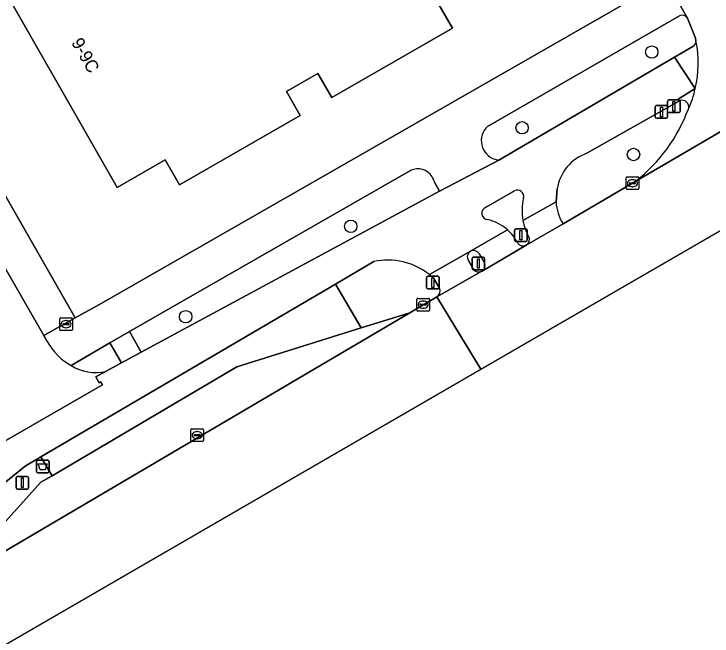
# Model space of a CAD drawing. Extents: x 158455 to 159797, y 387218 to 388672.
# Drawn here: x 159062 to 159117.1, y 387353.6 to 387402.7 of the extents above; entities that cross this region are included whole.
import ezdxf

# ---------------------------------------------------------------- set-up
doc = ezdxf.new("R2010")
doc.units = 0
for name, color, linetype in [('IMGEO_Afvalbak', 7, 'Continuous'), ('IMGEO_Berm_groen', 7, 'Continuous'), ('IMGEO_Boom', 7, 'Continuous'), ('IMGEO_Brandkraan', 7, 'Continuous'), ('IMGEO_Erf', 7, 'Continuous'), ('IMGEO_Fietspad_gesloten', 7, 'Continuous'), ('IMGEO_Fietspad_open', 7, 'Continuous'), ('IMGEO_Groenvoorziening', 7, 'Continuous'), ('IMGEO_Kolk', 7, 'Continuous'), ('IMGEO_Lichtmast', 7, 'Continuous'), ('IMGEO_Pand', 7, 'Continuous'), ('IMGEO_Pand_nummerreeks', 7, 'Continuous'), ('IMGEO_Rijbaan_lokaal_gesloten', 7, 'Continuous'), ('IMGEO_Rijbaan_lokaal_open', 7, 'Continuous'), ('IMGEO_Verkeerseiland_groen', 7, 'Continuous'), ('IMGEO_Verkeerseiland_open', 7, 'Continuous'), ('IMGEO_Verkeersregelinstallatiepaal', 7, 'Continuous'), ('IMGEO_Voetpad_open', 7, 'Continuous')]:
    doc.layers.add(name, color=color, linetype=linetype)

msp = doc.modelspace()

# ---------------------------------------------------------------- linework, layer by layer
at = {"layer": 'IMGEO_Afvalbak'}
for p, q in [((159063.771, 387366.587), (159063.771, 387367.387)), ((159063.771, 387367.387), (159063.771, 387366.587)), ((159063.871, 387367.487), (159064.661, 387367.487)), ((159064.661, 387367.487), (159063.871, 387367.487)), ((159064.761, 387367.387), (159064.761, 387366.587)), ((159064.761, 387366.587), (159064.761, 387367.387)), ((159064.661, 387366.487), (159063.871, 387366.487)), ((159063.871, 387366.487), (159064.661, 387366.487))]:
    msp.add_line(p, q, dxfattribs=at)
msp.add_lwpolyline([(159063.914, 387367.201), (159064.618, 387367.201), (159064.469, 387366.731), (159064.063, 387366.731), (159063.914, 387367.201)], dxfattribs=at)
for centre, start, end in [((159063.871, 387367.387), 90, 180), ((159063.871, 387367.387), 90, 180), ((159064.661, 387367.387), 0, 90), ((159064.661, 387367.387), 360, 90), ((159063.871, 387366.587), 180, 270), ((159063.871, 387366.587), 180, 270), ((159064.661, 387366.587), 270, 0), ((159064.661, 387366.587), 270, 0)]:
    msp.add_arc(centre, 0.1, start, end, dxfattribs=at)
at = {"layer": 'IMGEO_Berm_groen'}
for points in [[(159114.509, 387402.534), (159099.35, 387393.809)], [(159115.799, 387400.557), (159115.753, 387400.768), (159115.144, 387402.351)], [(159114.102, 387399.28), (159115.554, 387400.104)], [(159100.242, 387391.149), (159114.102, 387399.28)], [(159093.275, 387390.319), (159071.117, 387377.621), (159072.04, 387376.001), (159095.556, 387388.708)], [(159095.556, 387388.708), (159095.195, 387389.355)]]:
    msp.add_lwpolyline(points, dxfattribs=at)
msp.add_lwpolyline([(159038.659, 387347.178), (159053.231, 387355.576), (159056.88, 387357.739), (159064.12, 387365.736), (159065.004, 387366.253), (159064.118, 387367.746), (159062.871, 387366.998), (159053.387, 387359.328), (159051.34, 387358.173), (159035.521, 387349.101), (159024.831, 387342.952), (159003.155, 387330.485), (159003.462, 387329.964), (159005.167, 387327.132), (159026.581, 387340.034), (159027.914, 387340.837), (159037.173, 387346.301)], close=True, dxfattribs=at)
for centre, radius, start, end in [((159114.714, 387402.051), 0.525, 34.8953, 112.9519), ((159115.267, 387400.552), 0.532, 302.6578, 0.5297), ((159100.403, 387392.682), 1.542, 133.071, 252.4441), ((159100.405, 387392.699), 1.558, 252.5757, 264.0082), ((159093.873, 387389.167), 1.298, 31.0177, 117.437), ((159093.731, 387389.002), 1.506, 13.5475, 33.6237)]:
    msp.add_arc(centre, radius, start, end, dxfattribs=at)
at = {"layer": 'IMGEO_Boom'}
for centre in [(159112.312, 387399.672), (159102.081, 387393.697), (159110.87, 387391.593), (159088.565, 387385.923), (159075.542, 387378.796)]:
    msp.add_circle(centre, 0.489, dxfattribs=at)
at = {"layer": 'IMGEO_Brandkraan'}
for p, q in [((159065.603, 387377.783), (159065.603, 387378.635)), ((159065.678, 387378.709), (159066.53, 387378.709)), ((159066.604, 387378.635), (159066.604, 387377.783)), ((159065.862, 387378.203), (159065.862, 387378.215)), ((159066.3, 387378.166), (159065.902, 387378.166)), ((159065.905, 387378.252), (159066.303, 387378.252)), ((159066.091, 387378.489), (159066.116, 387378.489)), ((159066.346, 387378.215), (159066.346, 387378.203)), ((159066.53, 387377.709), (159065.678, 387377.709)), ((159066.114, 387377.929), (159066.089, 387377.929))]:
    msp.add_line(p, q, dxfattribs=at)
for points in [[(159065.603, 387377.783), (159065.603, 387378.635)], [(159065.678, 387378.709), (159066.53, 387378.709)], [(159066.604, 387378.635), (159066.604, 387377.783)], [(159066.53, 387377.709), (159065.678, 387377.709)]]:
    msp.add_lwpolyline(points, dxfattribs=at)
for centre, radius, start, end in [((159065.68, 387378.633), 0.0765, 91.552, 178.448), ((159065.68, 387378.633), 0.0765, 91.552, 178.448), ((159066.528, 387378.633), 0.0765, 1.552, 88.448), ((159066.528, 387378.633), 0.0765, 1.552, 88.448), ((159065.902, 387378.212), 0.0403, 85.8775, 175.7526), ((159065.899, 387378.202), 0.0366, 178.938, 274.7102), ((159066.303, 387378.209), 0.043, 264.8664, 352.4533), ((159066.307, 387378.214), 0.0386, 1.7309, 96.639), ((159065.68, 387377.785), 0.0765, 181.552, 268.448), ((159065.68, 387377.785), 0.0765, 181.552, 268.448), ((159066.528, 387377.785), 0.0765, 271.552, 358.448), ((159066.528, 387377.785), 0.0765, 271.552, 358.448)]:
    msp.add_arc(centre, radius, start, end, dxfattribs=at)
for centre, major_axis, ratio, start_param, end_param in [((159066.09, 387378.209), (-0.387, 0.002), 0.722429, 4.712389, 7.853982), ((159066.115, 387378.209), (-0.39, 0.002), 0.717154, 1.570796, 4.712389)]:
    msp.add_ellipse(centre, major_axis=major_axis, ratio=ratio, start_param=start_param, end_param=end_param, dxfattribs=at)
at = {"layer": 'IMGEO_Erf'}
for points in [[(159055.639, 387398.219), (159066.827, 387378.71), (159068.702, 387379.738), (159112.122, 387404.631), (159083.935, 387453.791)], [(159095.447, 387403.559), (159096.601, 387401.547), (159087.066, 387396.08), (159085.964, 387397.979), (159083.497, 387396.551), (159084.577, 387394.669), (159075.053, 387389.205), (159073.918, 387391.164), (159070.135, 387388.988), (159059.41, 387407.722)]]:
    msp.add_lwpolyline(points, dxfattribs=at)
at = {"layer": 'IMGEO_Fietspad_gesloten'}
for points in [[(159115.554, 387400.104), (159114.102, 387399.28), (159115.738, 387396.797)], [(159107.2, 387391.685), (159114.499, 387395.824), (159114.395, 387395.952), (159115.738, 387396.797), (159114.102, 387399.28), (159100.242, 387391.149), (159095.556, 387388.708), (159072.04, 387376.001), (159070.47, 387375.153), (159069.219, 387374.477), (159068.465, 387374.062), (159068.718, 387373.591), (159068.847, 387373.665), (159068.984, 387373.414), (159060.337, 387368.463), (159059.986, 387368.507)], [(159115.738, 387396.797), (159114.395, 387395.952), (159114.499, 387395.824)], [(159099.198, 387387.41), (159101.474, 387388.712)], [(159102.151, 387386.373), (159104.761, 387387.852), (159104.848, 387388.885)], [(159104.761, 387387.852), (159102.151, 387386.373)], [(159102.415, 387384.438), (159105.321, 387386.122)], [(159094.769, 387382.118), (159098.009, 387383.961), (159100.919, 387385.658)], [(159003.155, 387330.485), (159024.831, 387342.952), (159035.521, 387349.101), (159051.34, 387358.173), (159053.387, 387359.328), (159062.871, 387366.998), (159064.118, 387367.746), (159087.366, 387381.363), (159090.378, 387383.144)]]:
    msp.add_lwpolyline(points, dxfattribs=at)
for centre, radius, start, end in [((159115.267, 387400.552), 0.532, 302.6578, 0.5297), ((159107.355, 387398.813), 8.622, 346.4742, 11.6669), ((159109.652, 387397.919), 6.189, 333.702, 349.5555), ((159114.71, 387395.349), 0.52, 340.6614, 113.9267), ((159108.355, 387388.327), 3.552, 108.9861, 170.9534), ((159101.726, 387388.293), 0.489, 344.4726, 121.0055), ((159106.338, 387387.16), 4.26, 166.4022, 190.652), ((159108.383, 387388.069), 3.629, 183.4272, 212.4463), ((159099.41, 387386.955), 0.502, 114.9482, 263.0587), ((159098.586, 387383.015), 3.525, 48.559, 77.4964), ((159106.325, 387387.16), 4.247, 190.6791, 208.5526), ((159102.145, 387384.877), 0.515, 301.5865, 29.4079), ((159091.501, 387378.041), 5.225, 51.2867, 102.4098)]:
    msp.add_arc(centre, radius, start, end, dxfattribs=at)
at = {"layer": 'IMGEO_Fietspad_open'}
for points in [[(159064.609, 387376.853), (159064.348, 387377.307), (159051.673, 387399.357), (159051.509, 387399.66), (159048.505, 387397.967), (159047.199, 387397.231), (159059.985, 387374.909), (159060.23, 387374.481)], [(159100.919, 387385.658), (159098.009, 387383.961)], [(159098.92, 387382.393), (159102.415, 387384.438)], [(159098.701, 387383.771), (159099.116, 387383.057)], [(159059.986, 387368.507), (159060.337, 387368.463), (159068.984, 387373.414), (159068.847, 387373.665), (159068.718, 387373.591), (159068.465, 387374.062), (159069.219, 387374.477)]]:
    msp.add_lwpolyline(points, dxfattribs=at)
for centre, radius, start, end in [((159098.573, 387383), 3.545, 26.8409, 48.563), ((159102.162, 387384.881), 0.51, 213.263, 299.7392), ((159098.252, 387383.49), 0.53, 32.0229, 117.2708), ((159098.659, 387382.831), 0.51, 300.8175, 26.2914), ((159068.941, 387379.261), 4.956, 209.0739, 240.5646), ((159068.42, 387377.947), 3.561, 237.4675, 282.9649)]:
    msp.add_arc(centre, radius, start, end, dxfattribs=at)
at = {"layer": 'IMGEO_Groenvoorziening'}
for points in [[(159069.552, 387376.725), (159068.345, 387376.033), (159066.505, 387374.945)], [(159069.219, 387374.477), (159070.47, 387375.153), (159069.552, 387376.725)]]:
    msp.add_lwpolyline(points, dxfattribs=at)
msp.add_arc((159068.42, 387377.947), 3.561, 237.4675, 282.9649, dxfattribs=at)
at = {"layer": 'IMGEO_Kolk'}
for p, q in [((159110.293, 387388.899), (159110.293, 387389.751)), ((159110.368, 387389.825), (159111.22, 387389.825)), ((159111.294, 387389.751), (159111.294, 387388.899)), ((159110.552, 387389.319), (159110.552, 387389.331)), ((159110.99, 387389.282), (159110.592, 387389.282)), ((159110.595, 387389.368), (159110.993, 387389.368)), ((159110.781, 387389.605), (159110.806, 387389.605)), ((159111.036, 387389.331), (159111.036, 387389.319)), ((159111.22, 387388.825), (159110.368, 387388.825)), ((159110.804, 387389.045), (159110.779, 387389.045)), ((159093.781, 387379.318), (159093.781, 387380.17)), ((159093.856, 387380.244), (159094.708, 387380.244)), ((159094.04, 387379.738), (159094.04, 387379.75)), ((159094.083, 387379.787), (159094.481, 387379.787)), ((159094.269, 387380.024), (159094.294, 387380.024)), ((159094.524, 387379.75), (159094.524, 387379.738)), ((159094.782, 387380.17), (159094.782, 387379.318)), ((159094.708, 387379.244), (159093.856, 387379.244)), ((159094.478, 387379.701), (159094.08, 387379.701)), ((159094.292, 387379.464), (159094.267, 387379.464)), ((159075.943, 387369.025), (159075.943, 387369.877)), ((159076.018, 387369.951), (159076.87, 387369.951)), ((159076.944, 387369.877), (159076.944, 387369.025)), ((159076.202, 387369.445), (159076.202, 387369.457)), ((159076.64, 387369.408), (159076.242, 387369.408)), ((159076.245, 387369.494), (159076.643, 387369.494)), ((159076.431, 387369.731), (159076.456, 387369.731)), ((159076.686, 387369.457), (159076.686, 387369.445)), ((159076.87, 387368.951), (159076.018, 387368.951)), ((159076.454, 387369.171), (159076.429, 387369.171))]:
    msp.add_line(p, q, dxfattribs=at)
for points in [[(159110.293, 387388.899), (159110.293, 387389.751)], [(159110.368, 387389.825), (159111.22, 387389.825)], [(159111.294, 387389.751), (159111.294, 387388.899)], [(159111.22, 387388.825), (159110.368, 387388.825)], [(159093.781, 387379.318), (159093.781, 387380.17)], [(159093.856, 387380.244), (159094.708, 387380.244)], [(159094.782, 387380.17), (159094.782, 387379.318)], [(159094.708, 387379.244), (159093.856, 387379.244)], [(159075.943, 387369.025), (159075.943, 387369.877)], [(159076.018, 387369.951), (159076.87, 387369.951)], [(159076.944, 387369.877), (159076.944, 387369.025)], [(159076.87, 387368.951), (159076.018, 387368.951)]]:
    msp.add_lwpolyline(points, dxfattribs=at)
for centre, radius, start, end in [((159110.37, 387389.749), 0.0765, 91.552, 178.448), ((159110.37, 387389.749), 0.0765, 91.552, 178.448), ((159111.218, 387389.749), 0.0765, 1.552, 88.448), ((159111.218, 387389.749), 0.0765, 1.552, 88.448), ((159110.592, 387389.328), 0.0403, 85.8775, 175.7526), ((159110.589, 387389.318), 0.0366, 178.938, 274.7102), ((159110.993, 387389.325), 0.043, 264.8664, 352.4533), ((159110.997, 387389.33), 0.0386, 1.7309, 96.639), ((159110.37, 387388.901), 0.0765, 181.552, 268.448), ((159110.37, 387388.901), 0.0765, 181.552, 268.448), ((159111.218, 387388.901), 0.0765, 271.552, 358.448), ((159111.218, 387388.901), 0.0765, 271.552, 358.448), ((159093.858, 387380.168), 0.0765, 91.552, 178.448), ((159093.858, 387380.168), 0.0765, 91.552, 178.448), ((159094.08, 387379.747), 0.0403, 85.8775, 175.7526), ((159094.077, 387379.737), 0.0366, 178.938, 274.7102), ((159094.481, 387379.744), 0.043, 264.8664, 352.4533), ((159094.485, 387379.749), 0.0386, 1.7309, 96.639), ((159094.706, 387380.168), 0.0765, 1.552, 88.448), ((159094.706, 387380.168), 0.0765, 1.552, 88.448), ((159093.858, 387379.32), 0.0765, 181.552, 268.448), ((159093.858, 387379.32), 0.0765, 181.552, 268.448), ((159094.706, 387379.32), 0.0765, 271.552, 358.448), ((159094.706, 387379.32), 0.0765, 271.552, 358.448), ((159076.02, 387369.875), 0.0765, 91.552, 178.448), ((159076.02, 387369.875), 0.0765, 91.552, 178.448), ((159076.868, 387369.875), 0.0765, 1.552, 88.448), ((159076.868, 387369.875), 0.0765, 1.552, 88.448), ((159076.242, 387369.454), 0.0403, 85.8775, 175.7526), ((159076.239, 387369.444), 0.0366, 178.938, 274.7102), ((159076.643, 387369.451), 0.043, 264.8664, 352.4533), ((159076.647, 387369.456), 0.0386, 1.7309, 96.639), ((159076.02, 387369.027), 0.0765, 181.552, 268.448), ((159076.02, 387369.027), 0.0765, 181.552, 268.448), ((159076.868, 387369.027), 0.0765, 271.552, 358.448), ((159076.868, 387369.027), 0.0765, 271.552, 358.448)]:
    msp.add_arc(centre, radius, start, end, dxfattribs=at)
for centre, major_axis, ratio, start_param, end_param in [((159110.78, 387389.325), (-0.387, 0.002), 0.722429, 4.712389, 7.853982), ((159110.805, 387389.325), (-0.39, 0.002), 0.717154, 1.570796, 4.712389), ((159094.268, 387379.744), (-0.387, 0.002), 0.722429, 4.712389, 7.853982), ((159094.293, 387379.744), (-0.39, 0.002), 0.717154, 1.570796, 4.712389), ((159076.43, 387369.451), (-0.387, 0.002), 0.722429, 4.712389, 7.853982), ((159076.455, 387369.451), (-0.39, 0.002), 0.717154, 1.570796, 4.712389)]:
    msp.add_ellipse(centre, major_axis=major_axis, ratio=ratio, start_param=start_param, end_param=end_param, dxfattribs=at)
at = {"layer": 'IMGEO_Lichtmast'}
for p, q in [((159098.134, 387382.596), (159098.134, 387383.396)), ((159098.134, 387383.396), (159098.134, 387382.596)), ((159098.234, 387383.496), (159099.024, 387383.496)), ((159099.024, 387383.496), (159098.234, 387383.496)), ((159099.124, 387383.396), (159099.124, 387382.596)), ((159099.124, 387382.596), (159099.124, 387383.396)), ((159099.024, 387382.496), (159098.234, 387382.496)), ((159098.234, 387382.496), (159099.024, 387382.496)), ((159062.159, 387365.303), (159062.159, 387366.103)), ((159062.159, 387366.103), (159062.159, 387365.303)), ((159062.259, 387366.203), (159063.049, 387366.203)), ((159063.049, 387366.203), (159062.259, 387366.203)), ((159063.149, 387366.103), (159063.149, 387365.303)), ((159063.149, 387365.303), (159063.149, 387366.103)), ((159063.049, 387365.203), (159062.259, 387365.203)), ((159062.259, 387365.203), (159063.049, 387365.203))]:
    msp.add_line(p, q, dxfattribs=at)
for points in [[(159098.554, 387383.371), (159098.704, 387383.371), (159098.704, 387382.621), (159098.554, 387382.621), (159098.554, 387383.371)], [(159062.579, 387366.078), (159062.729, 387366.078), (159062.729, 387365.328), (159062.579, 387365.328), (159062.579, 387366.078)]]:
    msp.add_lwpolyline(points, dxfattribs=at)
for centre, start, end in [((159098.234, 387383.396), 90, 180), ((159098.234, 387383.396), 90, 180), ((159099.024, 387383.396), 0, 90), ((159099.024, 387383.396), 360, 90), ((159098.234, 387382.596), 180, 270), ((159098.234, 387382.596), 180, 270), ((159099.024, 387382.596), 270, 0), ((159099.024, 387382.596), 270, 0), ((159062.259, 387366.103), 90, 180), ((159062.259, 387366.103), 90, 180), ((159063.049, 387366.103), 0, 90), ((159063.049, 387366.103), 360, 90), ((159062.259, 387365.303), 180, 270), ((159062.259, 387365.303), 180, 270), ((159063.049, 387365.303), 270, 0), ((159063.049, 387365.303), 270, 0)]:
    msp.add_arc(centre, 0.1, start, end, dxfattribs=at)
at = {"layer": 'IMGEO_Pand'}
msp.add_lwpolyline([(159059.41, 387407.722), (159070.135, 387388.988), (159073.918, 387391.164), (159075.053, 387389.205), (159084.577, 387394.669), (159083.497, 387396.551), (159085.964, 387397.979), (159087.066, 387396.08), (159096.601, 387401.547), (159095.447, 387403.559)], dxfattribs=at)
at = {"layer": 'IMGEO_Rijbaan_lokaal_gesloten'}
for points in [[(159098.831, 387374.65), (159123.485, 387388.928), (159142.421, 387399.894), (159140.092, 387406.388), (159136.536, 387404.329), (159135.612, 387403.795), (159132.981, 387402.272), (159128.661, 387399.771), (159125.999, 387398.215), (159111.055, 387389.484), (159105.321, 387386.122), (159102.415, 387384.438), (159098.92, 387382.393), (159098.911, 387382.388), (159095.349, 387380.363), (159097.218, 387377.296), (159098.831, 387374.65)], [(158983.47, 387307.842), (159098.831, 387374.65), (159097.218, 387377.296), (159095.349, 387380.363), (159093.224, 387379.108), (159056.88, 387357.739), (159053.231, 387355.576), (159038.659, 387347.178), (159037.173, 387346.301), (159027.914, 387340.837), (159026.581, 387340.034), (159005.167, 387327.132), (159000, 387324.019)]]:
    msp.add_lwpolyline(points, dxfattribs=at)
msp.add_lwpolyline([(159089.386, 387377.932), (159079.588, 387374.834), (159065.004, 387366.253), (159064.12, 387365.736), (159056.88, 387357.739), (159093.224, 387379.108)], close=True, dxfattribs=at)
at = {"layer": 'IMGEO_Rijbaan_lokaal_open'}
msp.add_lwpolyline([(159089.386, 387377.932), (159087.366, 387381.363), (159064.118, 387367.746), (159065.004, 387366.253), (159079.588, 387374.834)], close=True, dxfattribs=at)
at = {"layer": 'IMGEO_Verkeerseiland_groen'}
for points in [[(159114.499, 387395.824), (159107.2, 387391.685)], [(159105.321, 387386.122), (159111.055, 387389.484)], [(159104.848, 387388.885), (159104.761, 387387.852)], [(159090.378, 387383.144), (159087.366, 387381.363), (159089.386, 387377.932), (159093.224, 387379.108), (159095.349, 387380.363)], [(159095.567, 387381.049), (159095.124, 387381.805), (159094.769, 387382.118)]]:
    msp.add_lwpolyline(points, dxfattribs=at)
for centre, radius, start, end in [((159114.71, 387395.349), 0.52, 340.6614, 113.9267), ((159102.902, 387399.776), 13.13, 308.3863, 339.4979), ((159108.355, 387388.327), 3.552, 108.9861, 170.9534), ((159108.383, 387388.069), 3.629, 183.4272, 212.4463), ((159091.501, 387378.041), 5.225, 51.2867, 102.4098), ((159095.075, 387380.828), 0.54, 300.5332, 24.2079)]:
    msp.add_arc(centre, radius, start, end, dxfattribs=at)
at = {"layer": 'IMGEO_Verkeerseiland_open'}
for points in [[(159101.474, 387388.712), (159099.198, 387387.41)], [(159099.116, 387383.057), (159098.701, 387383.771)], [(159097.843, 387383.235), (159098.234, 387382.567)], [(159098.911, 387382.388), (159098.92, 387382.393)]]:
    msp.add_lwpolyline(points, dxfattribs=at)
for centre, radius, start, end in [((159101.726, 387388.293), 0.489, 344.4726, 121.0055), ((159106.338, 387387.16), 4.26, 166.4022, 190.652), ((159099.41, 387386.955), 0.502, 114.9482, 263.0587), ((159098.586, 387383.015), 3.525, 48.559, 77.4964), ((159106.325, 387387.16), 4.247, 190.6791, 208.5526), ((159098.573, 387383), 3.545, 26.8409, 48.563), ((159102.145, 387384.877), 0.515, 301.5865, 29.4079), ((159102.162, 387384.881), 0.51, 213.263, 299.7392), ((159098.283, 387383.516), 0.522, 121.6651, 212.5764), ((159098.252, 387383.49), 0.53, 32.0229, 117.2708), ((159098.659, 387382.831), 0.51, 300.8175, 26.2914), ((159098.665, 387382.829), 0.504, 211.2368, 299.1428)]:
    msp.add_arc(centre, radius, start, end, dxfattribs=at)
at = {"layer": 'IMGEO_Verkeersregelinstallatiepaal'}
for p, q in [((159113.563, 387394.991), (159113.563, 387395.791)), ((159113.563, 387395.791), (159113.563, 387394.991)), ((159113.663, 387395.891), (159114.453, 387395.891)), ((159114.453, 387395.891), (159113.663, 387395.891)), ((159114.553, 387395.791), (159114.553, 387394.991)), ((159114.553, 387394.991), (159114.553, 387395.791)), ((159112.577, 387394.545), (159112.577, 387395.345)), ((159112.577, 387395.345), (159112.577, 387394.545)), ((159112.677, 387395.445), (159113.467, 387395.445)), ((159113.467, 387395.445), (159112.677, 387395.445)), ((159113.567, 387395.345), (159113.567, 387394.545)), ((159113.567, 387394.545), (159113.567, 387395.345)), ((159114.453, 387394.891), (159113.663, 387394.891)), ((159113.663, 387394.891), (159114.453, 387394.891)), ((159113.467, 387394.445), (159112.677, 387394.445)), ((159112.677, 387394.445), (159113.467, 387394.445)), ((159101.496, 387384.831), (159101.496, 387385.631)), ((159101.496, 387385.631), (159101.496, 387384.831)), ((159101.596, 387385.731), (159102.386, 387385.731)), ((159102.386, 387385.731), (159101.596, 387385.731)), ((159102.486, 387385.631), (159102.486, 387384.831)), ((159102.486, 387384.831), (159102.486, 387385.631)), ((159102.386, 387384.731), (159101.596, 387384.731)), ((159101.596, 387384.731), (159102.386, 387384.731)), ((159094.641, 387381.988), (159095.431, 387381.988)), ((159095.431, 387381.988), (159094.641, 387381.988)), ((159094.541, 387381.088), (159094.541, 387381.888)), ((159094.541, 387381.888), (159094.541, 387381.088)), ((159095.531, 387381.888), (159095.531, 387381.088)), ((159095.531, 387381.088), (159095.531, 387381.888)), ((159095.431, 387380.988), (159094.641, 387380.988)), ((159094.641, 387380.988), (159095.431, 387380.988))]:
    msp.add_line(p, q, dxfattribs=at)
for points in [[(159113.983, 387395.766), (159114.133, 387395.766), (159114.133, 387395.016), (159113.983, 387395.016), (159113.983, 387395.766)], [(159112.997, 387395.32), (159113.147, 387395.32), (159113.147, 387394.57), (159112.997, 387394.57), (159112.997, 387395.32)], [(159101.916, 387385.606), (159102.066, 387385.606), (159102.066, 387384.856), (159101.916, 387384.856), (159101.916, 387385.606)], [(159094.961, 387381.863), (159095.111, 387381.863), (159095.111, 387381.113), (159094.961, 387381.113), (159094.961, 387381.863)]]:
    msp.add_lwpolyline(points, dxfattribs=at)
for centre, start, end in [((159113.663, 387395.791), 90, 180), ((159113.663, 387395.791), 90, 180), ((159114.453, 387395.791), 0, 90), ((159114.453, 387395.791), 360, 90), ((159112.677, 387395.345), 90, 180), ((159112.677, 387395.345), 90, 180), ((159113.467, 387395.345), 0, 90), ((159113.467, 387395.345), 360, 90), ((159113.663, 387394.991), 180, 270), ((159113.663, 387394.991), 180, 270), ((159114.453, 387394.991), 270, 0), ((159114.453, 387394.991), 270, 0), ((159112.677, 387394.545), 180, 270), ((159112.677, 387394.545), 180, 270), ((159113.467, 387394.545), 270, 0), ((159113.467, 387394.545), 270, 0), ((159101.596, 387385.631), 90, 180), ((159101.596, 387385.631), 90, 180), ((159102.386, 387385.631), 0, 90), ((159102.386, 387385.631), 360, 90), ((159101.596, 387384.831), 180, 270), ((159101.596, 387384.831), 180, 270), ((159102.386, 387384.831), 270, 0), ((159102.386, 387384.831), 270, 0), ((159094.641, 387381.888), 90, 180), ((159094.641, 387381.888), 90, 180), ((159095.431, 387381.888), 0, 90), ((159095.431, 387381.888), 360, 90), ((159094.641, 387381.088), 180, 270), ((159094.641, 387381.088), 180, 270), ((159095.431, 387381.088), 270, 0), ((159095.431, 387381.088), 270, 0)]:
    msp.add_arc(centre, 0.1, start, end, dxfattribs=at)
at = {"layer": 'IMGEO_Voetpad_open'}
for points in [[(159125.451, 387398.465), (159123.937, 387401.136), (159122.047, 387404.465), (159121.927, 387404.839), (159121.862, 387405.28), (159121.965, 387406.64), (159122.102, 387406.886), (159122.482, 387410.602), (159122.174, 387410.426), (159114.462, 387406.015), (159114.05, 387405.783), (159113.425, 387405.379), (159115.144, 387402.351), (159115.753, 387400.768), (159115.799, 387400.557)], [(159115.144, 387402.351), (159113.425, 387405.379), (159112.122, 387404.631), (159068.702, 387379.738), (159066.827, 387378.71), (159064.348, 387377.307), (159064.609, 387376.853)], [(159099.35, 387393.809), (159114.509, 387402.534)], [(159051.673, 387399.357), (159064.348, 387377.307), (159066.827, 387378.71), (159055.639, 387398.219)], [(159111.055, 387389.484), (159125.999, 387398.215)], [(159095.195, 387389.355), (159095.556, 387388.708), (159100.242, 387391.149)], [(159066.505, 387374.945), (159068.345, 387376.033), (159069.552, 387376.725), (159071.117, 387377.621), (159093.275, 387390.319)], [(159098.009, 387383.961), (159094.769, 387382.118), (159095.124, 387381.805), (159095.567, 387381.049)], [(159098.234, 387382.567), (159097.843, 387383.235)], [(159095.349, 387380.363), (159098.911, 387382.388)]]:
    msp.add_lwpolyline(points, dxfattribs=at)
msp.add_lwpolyline([(159071.117, 387377.621), (159069.552, 387376.725), (159070.47, 387375.153), (159072.04, 387376.001)], close=True, dxfattribs=at)
for centre, radius, start, end in [((159114.714, 387402.051), 0.525, 34.8953, 112.9519), ((159107.355, 387398.813), 8.622, 346.4742, 11.6669), ((159109.652, 387397.919), 6.189, 333.702, 349.5555), ((159102.902, 387399.776), 13.13, 308.3863, 339.4979), ((159100.403, 387392.682), 1.542, 133.071, 252.4441), ((159100.405, 387392.699), 1.558, 252.5757, 264.0082), ((159093.873, 387389.167), 1.298, 31.0177, 117.437), ((159093.731, 387389.002), 1.506, 13.5475, 33.6237), ((159098.283, 387383.516), 0.522, 121.6651, 212.5764), ((159098.665, 387382.829), 0.504, 211.2368, 299.1428), ((159095.075, 387380.828), 0.54, 300.5332, 24.2079), ((159068.941, 387379.261), 4.956, 209.0739, 240.5646)]:
    msp.add_arc(centre, radius, start, end, dxfattribs=at)

# ---------------------------------------------------------------- texts
at = {"layer": 'IMGEO_Pand_nummerreeks'}
msp.add_text('9-9C', height=1, rotation=299.7908, dxfattribs=at).set_placement((159066.488, 387400.431))

doc.saveas('drawing.dxf')
